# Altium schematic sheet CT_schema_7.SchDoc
size 371 x 336 mm
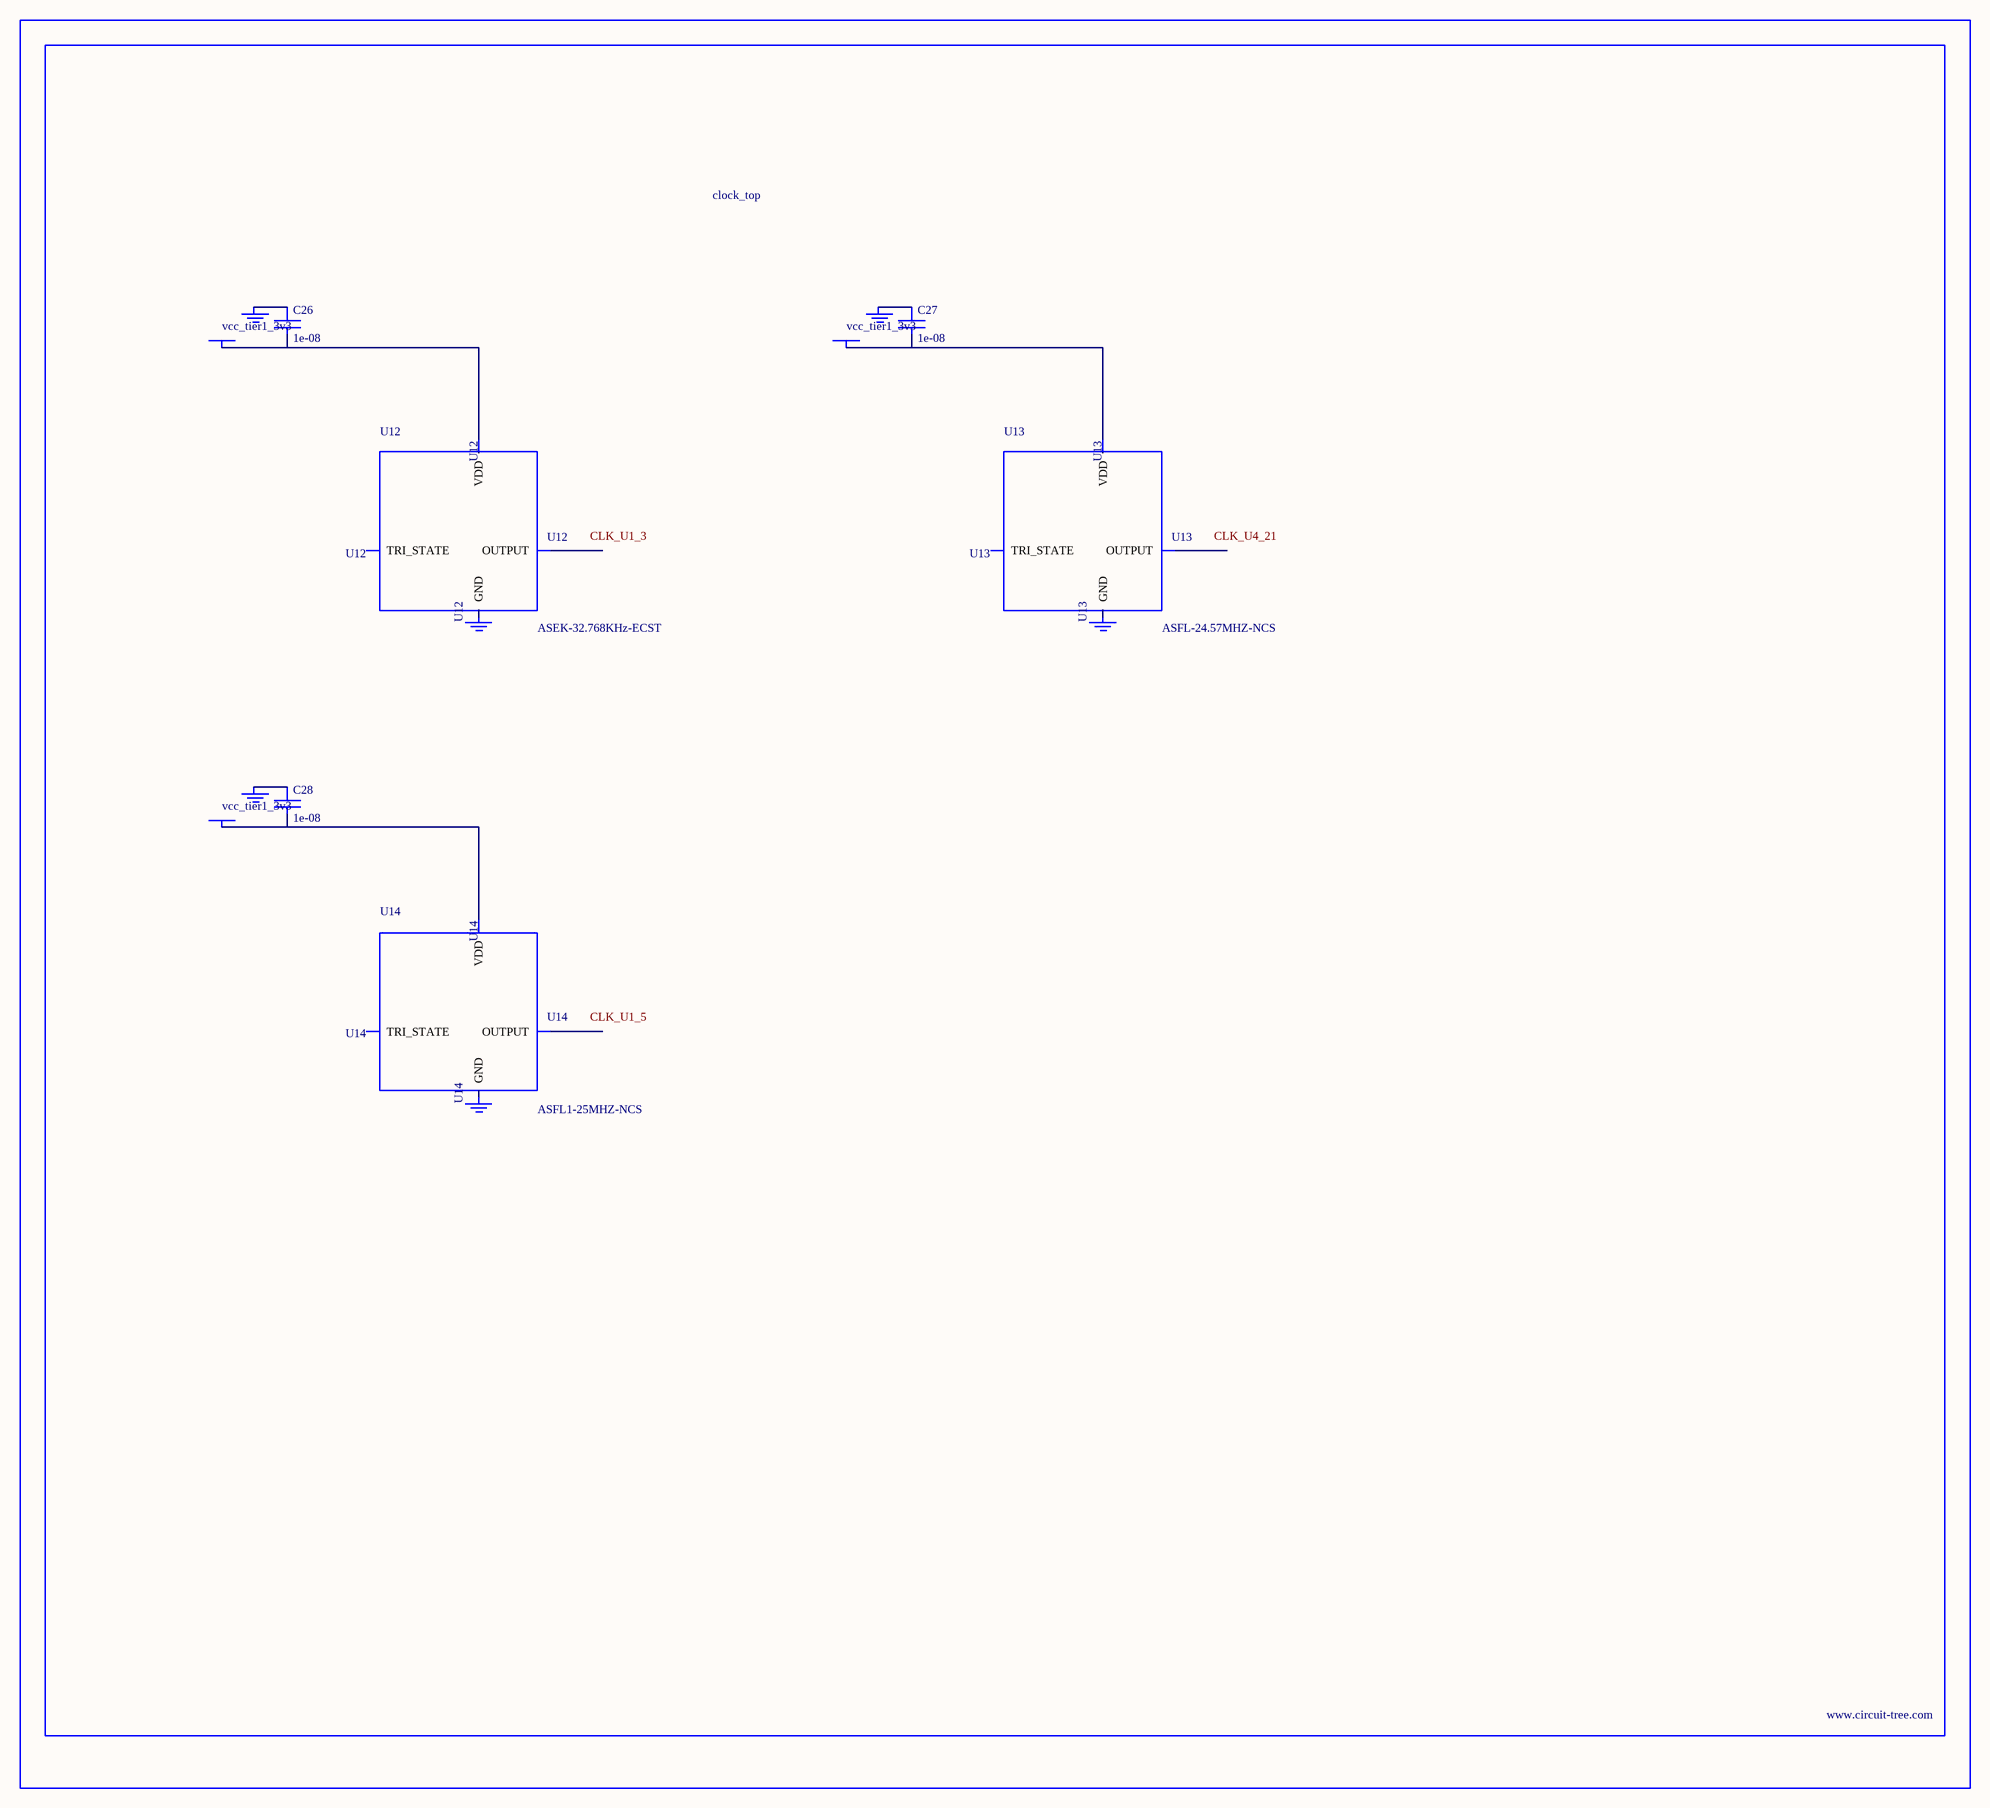
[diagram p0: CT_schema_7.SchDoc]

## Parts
BORDER6  (no value)
C26  1e-08  [C0402]
C27  1e-08  [C0402]
C28  1e-08  [C0402]
GND_INSTANCE_6_0  (no value)
GND_INSTANCE_6_1  (no value)
GND_INSTANCE_6_2  (no value)
GND_INSTANCE_6_3  (no value)
GND_INSTANCE_6_4  (no value)
GND_INSTANCE_6_5  (no value)
POWER_INSTANCE_6_0  vcc_tier1_3v3
POWER_INSTANCE_6_1  vcc_tier1_3v3
POWER_INSTANCE_6_2  vcc_tier1_3v3
U12  ASEK-32.768KHz-ECST  [ASEK]
U13  ASFL-24.57MHZ-NCS  [ASFL1]
U14  ASFL1-25MHZ-NCS  [ASFL1]

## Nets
NetC26_1: C26.1 GND_INSTANCE_6_0.0(GND)
NetC26_2: C26.2 POWER_INSTANCE_6_0.0(PWR) U12.4(VDD)
NetC27_1: C27.1 GND_INSTANCE_6_2.0(GND)
NetC27_2: C27.2 POWER_INSTANCE_6_1.0(PWR) U13.4(VDD)
NetC28_1: C28.1 GND_INSTANCE_6_4.0(GND)
NetC28_2: C28.2 POWER_INSTANCE_6_2.0(PWR) U14.4(VDD)

Not connected (* = marked no-connect by the designer): GND_INSTANCE_6_1 0(GND); GND_INSTANCE_6_3 0(GND); GND_INSTANCE_6_5 0(GND); U12 1(TRI_STATE) 2(GND) 3(OUTPUT); U13 1(TRI_STATE) 2(GND) 3(OUTPUT); U14 1(TRI_STATE) 2(GND) 3(OUTPUT)

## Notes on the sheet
- Labels drawn without touching a wire or pin: CLK_U1_3, CLK_U1_5, CLK_U4_21

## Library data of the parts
BORDER6 = BORDER_PAGE6
C26-C28 = C0402C103K3RAC
GND_INSTANCE_6_0-GND_INSTANCE_6_5 = GND
POWER_INSTANCE_6_0-POWER_INSTANCE_6_2 = PWR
